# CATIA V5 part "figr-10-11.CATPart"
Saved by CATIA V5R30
Part number: Part1
Bounding box of the stored display mesh (mm): x -100 to 0, y -100 to 90, z 0 to 33.608
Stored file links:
  D:\PROJECTS\CATIA V56R 2020\Resources\Parts File\c10_catia_v5_6r2020_prt\figr-10-11.CATPart
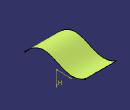
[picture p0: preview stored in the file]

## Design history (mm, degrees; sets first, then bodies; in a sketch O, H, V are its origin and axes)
Set1
  Sketch1 on face of yz-plane, origin (0, 0, 0), H (0, 0, -1), V (0, 1, 0)
    spline S1 through (0, -100) (-30, -20) (-10, 30) (-20, 90)
  Extrude1: Element1 Sketch1, Lim1 0, Lim2 100, Direction face of yz-plane
Body1 (main body)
